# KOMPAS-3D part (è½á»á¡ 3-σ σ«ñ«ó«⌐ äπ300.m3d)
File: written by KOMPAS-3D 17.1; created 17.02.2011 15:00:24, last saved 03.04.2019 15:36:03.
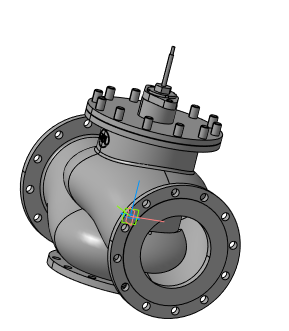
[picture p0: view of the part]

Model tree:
1. Плоскость XY
2. Плоскость ZX
3. Плоскость ZY
4. Ось X
5. Ось Y
6. Ось Z
7. Начало координат
8. Операция без истории:3

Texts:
  Клочков Андрей Владимирович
